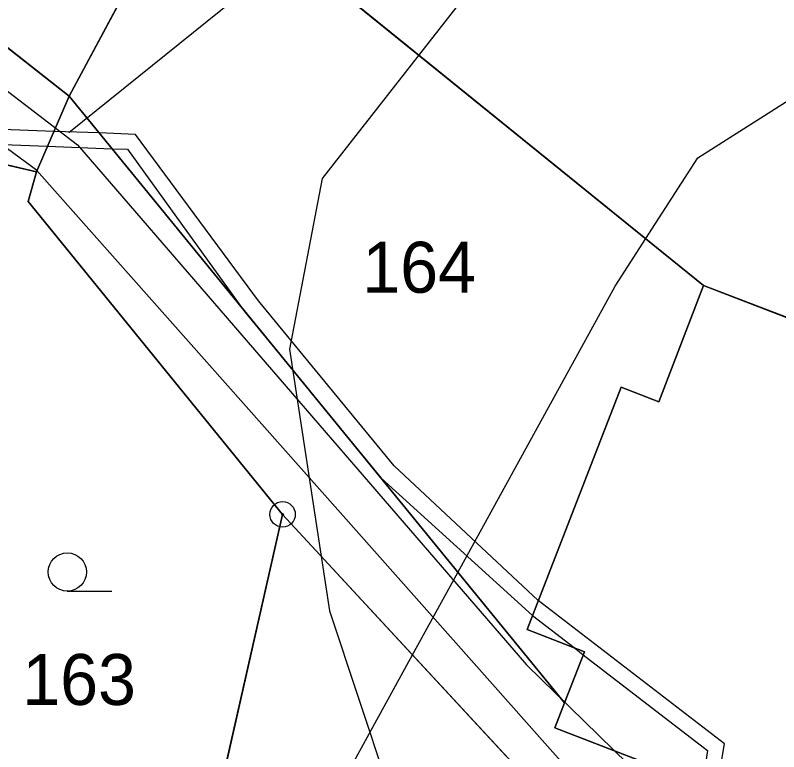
# Model space of a CAD drawing. Extents: x -706130 to -698555, y -971544 to -967260.
# Drawn here: x -704353.74 to -704323.76, y -970311.14 to -970282.24 of the extents above; entities that cross this region are included whole.
import ezdxf

# ---------------------------------------------------------------- set-up
doc = ezdxf.new("R2010")
doc.units = 0
for name, color, linetype in [('BPEJ hranice S', 7, 'Continuous'), ('BPEJ I-II trida ochrany S', 7, 'Continuous'), ('Docházková izochrona - BUS S', 7, 'Continuous'), ('Docházková izochrona - VLAK N', 7, 'Continuous'), ('Hranice intravilán', 7, 'Continuous'), ('Kanalizace_stoka bez rozlišení N', 7, 'Continuous'), ('KN_Hranice_parcel', 7, 'Continuous'), ('KN_Parcelni cisla', 7, 'Continuous'), ('KN_Polygon parcely', 7, 'Continuous'), ('KN_POZEMKY_14_OSTATNI PLOCHA', 7, 'Continuous'), ('KN_POZEMKY_5_ZAHRADA', 7, 'Continuous'), ('KN_POZEMKY_7_TTP', 7, 'Continuous'), ('KN_VYUZITI_17_ostatni plocha_ostatni komunikace', 7, 'Continuous'), ('KN_VYUZITI_26_ostatni plocha_jina plocha', 7, 'Continuous'), ('KN_Věcná břemena k části', 7, 'Continuous'), ('KN_Značky bodu BP', 7, 'Continuous'), ('KN_Značky kultur', 7, 'Continuous'), ('Plochy N_P ŠRAFY', 7, 'Continuous'), ('Plochy smíšené obytné venkovské N', 7, 'Continuous'), ('Plochy smíšené obytné venkovské S', 7, 'Continuous'), ('Plochy verejnych prostranstvi - komunikace ostatni S', 7, 'Continuous'), ('Plochy vodní a vodních toku_linie zatrubněný tok S', 7, 'Continuous'), ('Plochy zmen_ zastavitelne plochy', 7, 'Continuous'), ('Plochy zmen_ zastavitelne plochy_ZAKL', 7, 'Continuous'), ('Regulační bloky zastavitelné N', 7, 'Continuous'), ('Regulační bloky zastavěné S', 7, 'Continuous'), ('Vodovodní řady - rozváděcí S', 7, 'Continuous'), ('VÝŠKOPIS_vrstevnice hlavní', 7, 'Continuous'), ('Zastavene uzemi N', 7, 'Continuous'), ('Zastavene uzemi plochy N', 7, 'Continuous'), ('Zábory hodnocené - plochy', 7, 'Continuous'), ('Zábory hodnocené - prevzate z UPO I a II tridy ochrany ZPF', 7, 'Continuous')]:
    doc.layers.add(name, color=color, linetype=linetype)

msp = doc.modelspace()

# ---------------------------------------------------------------- linework, layer by layer
at = {"layer": 'BPEJ hranice S'}
msp.add_lwpolyline([(-704340.491, -970420.327), (-704347.35, -970405.438), (-704348.36, -970403.245), (-704349.853, -970400.004), (-704350.972, -970395.173), (-704355.353, -970376.26), (-704355.651, -970374.974), (-704355.738, -970374.596), (-704355.917, -970370.121), (-704356.358, -970359.104), (-704354.845, -970347.251), (-704354.524, -970344.734), (-704354.499, -970344.541), (-704348.702, -970326.597), (-704346.276, -970322.177), (-704338.133, -970307.344), (-704336.355, -970304.106), (-704330.184, -970292.866), (-704328.981, -970291.004), (-704326.933, -970287.838), (-704316.712, -970281.331)], dxfattribs=at)
at = {"layer": 'BPEJ I-II trida ochrany S'}
for p, q in [((-704351.62, -970285.42), (-704346.87, -970276.54)), ((-704346.87, -970276.54), (-704328.981, -970291.004)), ((-704360.67, -970278.29), (-704351.62, -970285.42)), ((-704352.9, -970288.39), (-704364.18, -970285.73)), ((-704353.23, -970289.55), (-704352.9, -970288.39)), ((-704343.24, -970301.83), (-704353.23, -970289.55)), ((-704346.4, -970315.76), (-704343.24, -970301.83))]:
    msp.add_line(p, q, dxfattribs=at)
msp.add_lwpolyline([(-704328.981, -970291.004), (-704326.933, -970287.838), (-704316.712, -970281.331), (-704302.465, -970273.895), (-704289.146, -970269.867), (-704280.282, -970270.201), (-704280.282, -970270.201)], dxfattribs=at)
at = {"layer": 'Docházková izochrona - BUS S'}
msp.add_arc((-704361.829, -969946.93), 400, 155.51821, 17.33949, dxfattribs=at)
at = {"layer": 'Docházková izochrona - VLAK N'}
msp.add_circle((-704165.451, -969778.767), 800, dxfattribs=at)
at = {"layer": 'Hranice intravilán'}
msp.add_lwpolyline([(-704346.87, -970276.54), (-704326.71, -970292.84), (-704284.63, -970309.07), (-704263.93, -970315.92), (-704273.85, -970327.8), (-704279.276, -970333.968), (-704304.8, -970330.37), (-704311.244, -970330.02), (-704299.1, -970339.11), (-704282.96, -970351.19), (-704280.06, -970350.39), (-704279.31, -970342.55), (-704272.47, -970343.16), (-704272.98, -970348.43), (-704263.51, -970345.81), (-704260.19, -970378.07)], dxfattribs=at)
at = {"layer": 'Kanalizace_stoka bez rozlišení N'}
msp.add_lwpolyline([(-704365.425, -970272.107), (-704361.93, -970279.157), (-704351.294, -970287.322), (-704333.664, -970307.736), (-704327.981, -970313.277), (-704302.192, -970326.4), (-704254.693, -970332.232)], dxfattribs=at)
at = {"layer": 'KN_Hranice_parcel'}
for p, q in [((-704351.62, -970285.42), (-704346.87, -970276.54)), ((-704326.71, -970292.84), (-704346.87, -970276.54)), ((-704352.9, -970288.39), (-704351.62, -970285.42)), ((-704351.62, -970285.42), (-704332.17, -970309.23)), ((-704346.4, -970315.76), (-704343.24, -970301.83)), ((-704343.24, -970301.83), (-704330.44, -970315.65))]:
    msp.add_line(p, q, dxfattribs=at)
for points in [[(-704348.38, -970249.44), (-704352.3, -970258.94), (-704360.67, -970278.29), (-704351.62, -970285.42)], [(-704352.9, -970288.39), (-704364.18, -970285.73), (-704369.23, -970310.61)], [(-704343.24, -970301.83), (-704353.23, -970289.55), (-704352.9, -970288.39)], [(-704332.17, -970309.23), (-704331.39, -970307.22), (-704333.64, -970306.35), (-704329.95, -970296.83), (-704328.47, -970297.41), (-704326.71, -970292.84)], [(-704326.71, -970292.84), (-704284.63, -970309.07), (-704263.93, -970315.92)], [(-704273.85, -970327.8), (-704291.07, -970325.77), (-704291.83, -970327.73), (-704299.48, -970324.78), (-704303.83, -970324.27), (-704326.2, -970312.65), (-704332.55, -970310.21), (-704332.17, -970309.23)]]:
    msp.add_lwpolyline(points, dxfattribs=at)
at = {"layer": 'KN_Polygon parcely'}
for points in [[(-704266.41, -970278.02), (-704277.06, -970272.43), (-704285.92, -970266.3), (-704300.46, -970253.7), (-704322.9, -970229.9), (-704325.34, -970227.68), (-704336.11, -970255.37), (-704346.87, -970276.54), (-704326.71, -970292.84), (-704284.63, -970309.07), (-704263.93, -970315.92)], [(-704361.08, -970269.38), (-704366.65, -970284.79), (-704368.75, -970300.09), (-704369.23, -970310.61), (-704364.18, -970285.73), (-704352.9, -970288.39), (-704351.62, -970285.42), (-704360.67, -970278.29), (-704352.3, -970258.94), (-704348.38, -970249.44), (-704350.46, -970248.43)], [(-704352.3, -970258.94), (-704360.67, -970278.29), (-704351.62, -970285.42), (-704346.87, -970276.54), (-704336.11, -970255.37), (-704348.38, -970249.44)], [(-704326.71, -970292.84), (-704346.87, -970276.54), (-704351.62, -970285.42), (-704332.17, -970309.23), (-704331.39, -970307.22), (-704333.64, -970306.35), (-704329.95, -970296.83), (-704328.47, -970297.41)], [(-704267.89, -970328.65), (-704273.85, -970327.8), (-704291.07, -970325.77), (-704291.83, -970327.73), (-704299.48, -970324.78), (-704303.83, -970324.27), (-704326.2, -970312.65), (-704332.55, -970310.21), (-704332.17, -970309.23), (-704351.62, -970285.42), (-704352.9, -970288.39), (-704353.23, -970289.55), (-704343.24, -970301.83), (-704330.44, -970315.65), (-704304.8, -970330.37), (-704268.2, -970335.53)], [(-704346.4, -970315.76), (-704343.24, -970301.83), (-704353.23, -970289.55), (-704352.9, -970288.39), (-704364.18, -970285.73), (-704369.23, -970310.61), (-704369.52, -970316.88), (-704353.87, -970316.12)], [(-704263.93, -970315.92), (-704284.63, -970309.07), (-704326.71, -970292.84), (-704328.47, -970297.41), (-704329.95, -970296.83), (-704333.64, -970306.35), (-704331.39, -970307.22), (-704332.17, -970309.23), (-704332.55, -970310.21), (-704326.2, -970312.65), (-704303.83, -970324.27), (-704299.48, -970324.78), (-704291.83, -970327.73), (-704291.07, -970325.77), (-704273.85, -970327.8)], [(-704343.96, -970324.73), (-704331.11, -970326.26), (-704330.44, -970315.65), (-704343.24, -970301.83), (-704346.4, -970315.76), (-704346.34, -970319.08), (-704343.76, -970319.32)]]:
    msp.add_lwpolyline(points, close=True, dxfattribs=at)
at = {"layer": 'KN_POZEMKY_14_OSTATNI PLOCHA'}
for p, q in [((-704351.62, -970285.42), (-704346.87, -970276.54)), ((-704346.87, -970276.54), (-704326.71, -970292.84)), ((-704360.67, -970278.29), (-704351.62, -970285.42)), ((-704351.62, -970285.42), (-704352.9, -970288.39)), ((-704352.9, -970288.39), (-704351.62, -970285.42)), ((-704351.62, -970285.42), (-704332.17, -970309.23)), ((-704332.17, -970309.23), (-704351.62, -970285.42)), ((-704352.9, -970288.39), (-704364.18, -970285.73)), ((-704353.23, -970289.55), (-704352.9, -970288.39)), ((-704343.24, -970301.83), (-704353.23, -970289.55)), ((-704326.71, -970292.84), (-704328.47, -970297.41)), ((-704328.47, -970297.41), (-704326.71, -970292.84)), ((-704326.71, -970292.84), (-704284.63, -970309.07)), ((-704329.95, -970296.83), (-704333.64, -970306.35)), ((-704333.64, -970306.35), (-704329.95, -970296.83)), ((-704328.47, -970297.41), (-704329.95, -970296.83)), ((-704329.95, -970296.83), (-704328.47, -970297.41)), ((-704346.4, -970315.76), (-704343.24, -970301.83)), ((-704330.44, -970315.65), (-704343.24, -970301.83)), ((-704343.24, -970301.83), (-704330.44, -970315.65)), ((-704333.64, -970306.35), (-704331.39, -970307.22)), ((-704331.39, -970307.22), (-704333.64, -970306.35)), ((-704331.39, -970307.22), (-704332.17, -970309.23)), ((-704332.17, -970309.23), (-704331.39, -970307.22)), ((-704332.17, -970309.23), (-704332.55, -970310.21)), ((-704332.55, -970310.21), (-704332.17, -970309.23)), ((-704332.55, -970310.21), (-704326.2, -970312.65)), ((-704326.2, -970312.65), (-704332.55, -970310.21))]:
    msp.add_line(p, q, dxfattribs=at)
at = {"layer": 'KN_POZEMKY_5_ZAHRADA'}
for p, q in [((-704346.87, -970276.54), (-704351.62, -970285.42)), ((-704351.62, -970285.42), (-704360.67, -970278.29)), ((-704364.18, -970285.73), (-704352.9, -970288.39)), ((-704352.9, -970288.39), (-704353.23, -970289.55)), ((-704353.23, -970289.55), (-704343.24, -970301.83)), ((-704343.24, -970301.83), (-704346.4, -970315.76))]:
    msp.add_line(p, q, dxfattribs=at)
at = {"layer": 'KN_POZEMKY_7_TTP'}
for p, q in [((-704326.71, -970292.84), (-704346.87, -970276.54)), ((-704284.63, -970309.07), (-704326.71, -970292.84))]:
    msp.add_line(p, q, dxfattribs=at)
at = {"layer": 'KN_VYUZITI_17_ostatni plocha_ostatni komunikace'}
for p, q in [((-704360.67, -970278.29), (-704351.62, -970285.42)), ((-704351.62, -970285.42), (-704352.9, -970288.39)), ((-704352.9, -970288.39), (-704351.62, -970285.42)), ((-704351.62, -970285.42), (-704332.17, -970309.23)), ((-704352.9, -970288.39), (-704364.18, -970285.73)), ((-704353.23, -970289.55), (-704352.9, -970288.39)), ((-704343.24, -970301.83), (-704353.23, -970289.55)), ((-704330.44, -970315.65), (-704343.24, -970301.83)), ((-704332.17, -970309.23), (-704332.55, -970310.21)), ((-704332.55, -970310.21), (-704326.2, -970312.65))]:
    msp.add_line(p, q, dxfattribs=at)
at = {"layer": 'KN_VYUZITI_26_ostatni plocha_jina plocha'}
for p, q in [((-704351.62, -970285.42), (-704346.87, -970276.54)), ((-704346.87, -970276.54), (-704326.71, -970292.84)), ((-704332.17, -970309.23), (-704351.62, -970285.42)), ((-704326.71, -970292.84), (-704328.47, -970297.41)), ((-704328.47, -970297.41), (-704326.71, -970292.84)), ((-704326.71, -970292.84), (-704284.63, -970309.07)), ((-704329.95, -970296.83), (-704333.64, -970306.35)), ((-704333.64, -970306.35), (-704329.95, -970296.83)), ((-704328.47, -970297.41), (-704329.95, -970296.83)), ((-704329.95, -970296.83), (-704328.47, -970297.41)), ((-704346.4, -970315.76), (-704343.24, -970301.83)), ((-704343.24, -970301.83), (-704330.44, -970315.65)), ((-704333.64, -970306.35), (-704331.39, -970307.22)), ((-704331.39, -970307.22), (-704333.64, -970306.35)), ((-704331.39, -970307.22), (-704332.17, -970309.23)), ((-704332.17, -970309.23), (-704331.39, -970307.22)), ((-704332.55, -970310.21), (-704332.17, -970309.23)), ((-704326.2, -970312.65), (-704332.55, -970310.21))]:
    msp.add_line(p, q, dxfattribs=at)
at = {"layer": 'KN_Věcná břemena k části'}
for points in [[(-704326.14, -970312.31), (-704325.89, -970310.84), (-704333.2, -970305.21), (-704338.86, -970299.93), (-704344.19, -970293.45), (-704349.01, -970286.92), (-704350.44, -970286.86), (-704352.21, -970286.8), (-704357.29, -970286.6)], [(-704357.35, -970287.2), (-704352.47, -970287.38), (-704349.94, -970287.48), (-704349.33, -970287.5), (-704344.73, -970293.86), (-704339.37, -970300.41), (-704333.43, -970305.8), (-704331.79, -970307.06), (-704331.44, -970307.34), (-704326.55, -970311.1), (-704326.7, -970312.05)]]:
    msp.add_lwpolyline(points, dxfattribs=at)
at = {"layer": 'KN_Značky bodu BP'}
for radius in [0.5, 0.0303]:
    msp.add_circle((-704343.24, -970301.83), radius, dxfattribs=at)
at = {"layer": 'KN_Značky kultur'}
msp.add_line((-704351.693, -970304.84), (-704349.943, -970304.84), dxfattribs=at)
msp.add_circle((-704351.693, -970304.09), 0.75, dxfattribs=at)
at = {"layer": 'Plochy N_P ŠRAFY'}
for p, q in [((-704346.87, -970276.54), (-704351.62, -970285.42)), ((-704351.62, -970285.42), (-704332.17, -970309.23)), ((-704332.17, -970309.23), (-704332.55, -970310.21))]:
    msp.add_line(p, q, dxfattribs=at)
msp.add_lwpolyline([(-704332.55, -970310.21), (-704326.2, -970312.65), (-704303.83, -970324.27), (-704299.48, -970324.78)], dxfattribs=at)
at = {"layer": 'Plochy smíšené obytné venkovské N'}
for p, q in [((-704346.87, -970276.54), (-704351.62, -970285.42)), ((-704351.62, -970285.42), (-704332.17, -970309.23)), ((-704332.17, -970309.23), (-704332.55, -970310.21))]:
    msp.add_line(p, q, dxfattribs=at)
msp.add_lwpolyline([(-704332.55, -970310.21), (-704326.2, -970312.65), (-704303.83, -970324.27), (-704299.48, -970324.78)], dxfattribs=at)
at = {"layer": 'Plochy smíšené obytné venkovské S'}
for p, q in [((-704351.62, -970285.42), (-704346.87, -970276.54)), ((-704360.67, -970278.29), (-704351.62, -970285.42)), ((-704330.44, -970315.65), (-704343.24, -970301.83))]:
    msp.add_line(p, q, dxfattribs=at)
for points in [[(-704352.9, -970288.39), (-704364.18, -970285.73), (-704369.23, -970310.61)], [(-704343.24, -970301.83), (-704353.23, -970289.55), (-704352.9, -970288.39)]]:
    msp.add_lwpolyline(points, dxfattribs=at)
at = {"layer": 'Plochy verejnych prostranstvi - komunikace ostatni S'}
for p, q in [((-704351.62, -970285.42), (-704360.67, -970278.29)), ((-704332.17, -970309.23), (-704351.62, -970285.42)), ((-704364.18, -970285.73), (-704352.9, -970288.39)), ((-704343.24, -970301.83), (-704330.44, -970315.65)), ((-704332.55, -970310.21), (-704332.17, -970309.23))]:
    msp.add_line(p, q, dxfattribs=at)
for points in [[(-704352.9, -970288.39), (-704353.23, -970289.55), (-704343.24, -970301.83)], [(-704299.48, -970324.78), (-704303.83, -970324.27), (-704326.2, -970312.65), (-704332.55, -970310.21)]]:
    msp.add_lwpolyline(points, dxfattribs=at)
at = {"layer": 'Plochy vodní a vodních toku_linie zatrubněný tok S'}
msp.add_lwpolyline([(-704351.63, -970286.842), (-704343.453, -970280.248), (-704322.195, -970231.658)], dxfattribs=at)
at = {"layer": 'Plochy zmen_ zastavitelne plochy'}
msp.add_lwpolyline([(-704229.72, -970332.943), (-704247, -970331.4), (-704250.33, -970331.1), (-704254.81, -970330.48), (-704267.89, -970328.65), (-704273.85, -970327.8), (-704291.07, -970325.77), (-704291.83, -970327.73), (-704299.48, -970324.78), (-704303.83, -970324.27), (-704326.2, -970312.65), (-704332.55, -970310.21), (-704332.17, -970309.23), (-704351.62, -970285.42), (-704346.87, -970276.54)], dxfattribs=at)
at = {"layer": 'Plochy zmen_ zastavitelne plochy_ZAKL'}
for p, q in [((-704346.87, -970276.54), (-704351.62, -970285.42)), ((-704351.62, -970285.42), (-704332.17, -970309.23)), ((-704332.17, -970309.23), (-704332.55, -970310.21))]:
    msp.add_line(p, q, dxfattribs=at)
msp.add_lwpolyline([(-704332.55, -970310.21), (-704326.2, -970312.65), (-704303.83, -970324.27), (-704299.48, -970324.78)], dxfattribs=at)
at = {"layer": 'Regulační bloky zastavitelné N'}
for p, q in [((-704346.87, -970276.54), (-704351.62, -970285.42)), ((-704351.62, -970285.42), (-704332.17, -970309.23)), ((-704332.17, -970309.23), (-704332.55, -970310.21))]:
    msp.add_line(p, q, dxfattribs=at)
msp.add_lwpolyline([(-704332.55, -970310.21), (-704326.2, -970312.65), (-704303.83, -970324.27), (-704299.48, -970324.78)], dxfattribs=at)
at = {"layer": 'Regulační bloky zastavěné S'}
for p, q in [((-704351.62, -970285.42), (-704346.87, -970276.54)), ((-704360.67, -970278.29), (-704351.62, -970285.42)), ((-704351.62, -970285.42), (-704360.67, -970278.29)), ((-704332.17, -970309.23), (-704351.62, -970285.42)), ((-704364.18, -970285.73), (-704352.9, -970288.39)), ((-704330.44, -970315.65), (-704343.24, -970301.83)), ((-704343.24, -970301.83), (-704330.44, -970315.65)), ((-704332.55, -970310.21), (-704332.17, -970309.23))]:
    msp.add_line(p, q, dxfattribs=at)
for points in [[(-704352.9, -970288.39), (-704364.18, -970285.73), (-704369.23, -970310.61)], [(-704343.24, -970301.83), (-704353.23, -970289.55), (-704352.9, -970288.39)], [(-704352.9, -970288.39), (-704353.23, -970289.55), (-704343.24, -970301.83)], [(-704299.48, -970324.78), (-704303.83, -970324.27), (-704326.2, -970312.65), (-704332.55, -970310.21)]]:
    msp.add_lwpolyline(points, dxfattribs=at)
at = {"layer": 'Vodovodní řady - rozváděcí S'}
msp.add_lwpolyline([(-704066.07, -970359.909), (-704122.844, -970354.44), (-704176.342, -970341.902), (-704264.987, -970332.825), (-704265.675, -970332.748), (-704302.701, -970328.63), (-704329.849, -970314.291), (-704352.898, -970288.323), (-704360.831, -970282.5), (-704370.399, -970278.264)], dxfattribs=at)
at = {"layer": 'VÝŠKOPIS_vrstevnice hlavní'}
msp.add_lwpolyline([(-704335.549, -970280.793), (-704341.684, -970288.64), (-704342.968, -970295.346), (-704341.399, -970305.618), (-704339.116, -970312.466), (-704330.841, -970329.587), (-704325.848, -970350.131), (-704324.991, -970363.828), (-704325.562, -970377.524), (-704326.846, -970384.372), (-704329.414, -970391.22), (-704331.412, -970394.644), (-704334.123, -970397.498), (-704340.258, -970402.063), (-704344.395, -970403.062), (-704348.96, -970402.776), (-704357.949, -970397.926), (-704361.943, -970390.364), (-704367.365, -970370.105), (-704372.222, -970358.306)], dxfattribs=at)
at = {"layer": 'Zastavene uzemi N'}
msp.add_lwpolyline([(-704394.69, -970423.1), (-704386.46, -970409.76), (-704381.94, -970403.15), (-704349.12, -970414.28), (-704347.89, -970396.42), (-704346.81, -970380.86), (-704296.54, -970360.34), (-704279.43, -970359.72), (-704281.91, -970379.77), (-704260.19, -970378.07), (-704263.51, -970345.81), (-704239.25, -970338.43), (-704251.29, -970337.91), (-704268.2, -970335.53), (-704267.89, -970328.65), (-704273.85, -970327.8), (-704263.93, -970315.92), (-704284.63, -970309.07), (-704326.71, -970292.84), (-704346.87, -970276.54)], dxfattribs=at)
at = {"layer": 'Zastavene uzemi plochy N'}
msp.add_lwpolyline([(-704394.69, -970423.1), (-704386.46, -970409.76), (-704381.94, -970403.15), (-704349.12, -970414.28), (-704347.89, -970396.42), (-704346.81, -970380.86), (-704296.54, -970360.34), (-704279.43, -970359.72), (-704281.91, -970379.77), (-704260.19, -970378.07), (-704263.51, -970345.81), (-704239.25, -970338.43), (-704251.29, -970337.91), (-704268.2, -970335.53), (-704267.89, -970328.65), (-704273.85, -970327.8), (-704263.93, -970315.92), (-704284.63, -970309.07), (-704326.71, -970292.84), (-704346.87, -970276.54)], dxfattribs=at)
at = {"layer": 'Zábory hodnocené - plochy'}
for p, q in [((-704346.87, -970276.54), (-704351.62, -970285.42)), ((-704351.62, -970285.42), (-704332.17, -970309.23)), ((-704332.17, -970309.23), (-704332.55, -970310.21))]:
    msp.add_line(p, q, dxfattribs=at)
msp.add_lwpolyline([(-704332.55, -970310.21), (-704326.2, -970312.65), (-704303.83, -970324.27), (-704299.48, -970324.78)], dxfattribs=at)
at = {"layer": 'Zábory hodnocené - prevzate z UPO I a II tridy ochrany ZPF'}
for p, q in [((-704346.87, -970276.54), (-704351.62, -970285.42)), ((-704351.62, -970285.42), (-704332.17, -970309.23)), ((-704332.17, -970309.23), (-704332.55, -970310.21))]:
    msp.add_line(p, q, dxfattribs=at)
msp.add_lwpolyline([(-704332.55, -970310.21), (-704326.2, -970312.65), (-704303.83, -970324.27), (-704299.48, -970324.78)], dxfattribs=at)

# ---------------------------------------------------------------- texts
at = {"layer": 'KN_Parcelni cisla'}
for s, p in [('164', (-704340.11, -970293.13)), ('163', (-704353.46, -970309.309))]:
    msp.add_text(s, height=2, dxfattribs=at).set_placement(p)

doc.saveas('drawing.dxf')
